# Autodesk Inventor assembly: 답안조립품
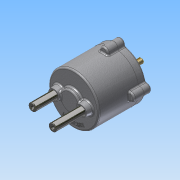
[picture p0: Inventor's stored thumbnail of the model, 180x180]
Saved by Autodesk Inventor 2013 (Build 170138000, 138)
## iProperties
Created: 2015-02
Part Number: 답안조립품
Document SubType Name: Assembly
Designer: WINDOWS7
Author: WINDOWS7
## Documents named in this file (13)
- C:\Users\WINDOWS7\Desktop\350208V1009\답안조립품.iam
- C:\Users\WINDOWS7\Desktop\350208V1009\몸체.ipt
- C:\Users\WINDOWS7\Desktop\350208V1009\커버.ipt
- C:\Users\WINDOWS7\Desktop\350208V1009\베어링 NA 4900.ipt
- C:\Users\WINDOWS7\Desktop\350208V1009\오일실.ipt
- C:\Users\WINDOWS7\Desktop\350208V1009\M5x0.5x20.ipt
- C:\Users\WINDOWS7\Desktop\350208V1009\메인 축.ipt
- C:\Users\WINDOWS7\Desktop\350208V1009\멈춤링 22 x 1.2.ipt
- C:\Users\WINDOWS7\Desktop\350208V1009\멈춤링 10 x 1.ipt
- C:\Users\WINDOWS7\Desktop\350208V1009\판캠.ipt
- C:\Users\WINDOWS7\Desktop\350208V1009\슬라이드 축.ipt
- C:\Users\WINDOWS7\Desktop\350208V1009\가변스프링1.ipt
- C:\Users\WINDOWS7\Desktop\350208V1009\가변스프링2.ipt
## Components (6 placed, 3 different names)
1. 가변스프링1:1
2. 가변스프링2:1
3. M5x0.5x20:1
4. M5x0.5x20:2
5. M5x0.5x20:3
6. M5x0.5x20:4
